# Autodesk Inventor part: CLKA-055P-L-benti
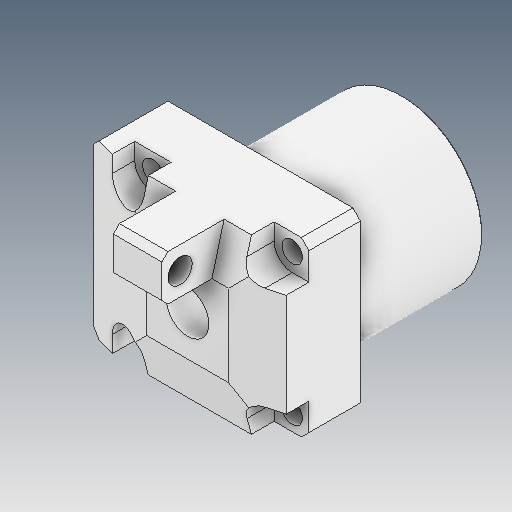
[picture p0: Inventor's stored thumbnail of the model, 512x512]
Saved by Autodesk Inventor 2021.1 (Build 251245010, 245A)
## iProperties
Created: 2021-06
Part Number: CLKA-055P-L-benti
Material: Ogólny
Document SubType Name: Modeling
Designer: user
Density: 1 g/cm^3
Appearance: Domyślna
Author: user
Revision Number: ÈÎºÎ
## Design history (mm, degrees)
feature "ÇÐ³ý-Ðý×ª5"
node "Bryła1"
